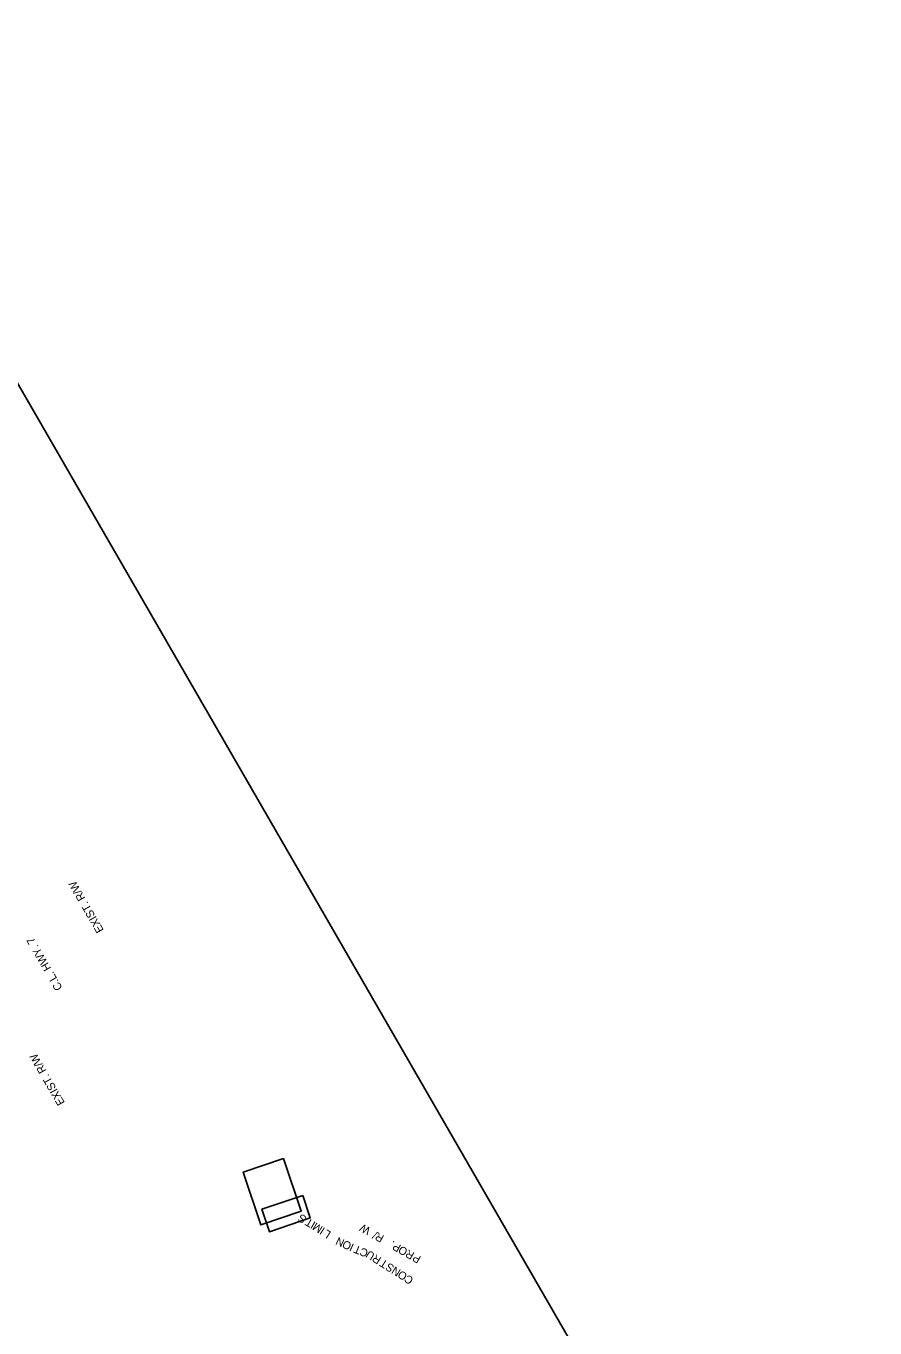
# Model space of a CAD drawing. Extents: x 956270 to 957915, y 1920230 to 1922423.
# Drawn here: x 957279 to 957915, y 1921447 to 1922423 of the extents above; entities that cross this region are included whole.
import ezdxf

# ---------------------------------------------------------------- set-up
doc = ezdxf.new("R2010")
doc.units = 0
doc.layers.add('NO PLOT', color=7, linetype='Continuous')
doc.layers.add('R_Draft', color=7, linetype='Continuous')

msp = doc.modelspace()

# ---------------------------------------------------------------- linework, layer by layer
at = {"layer": 'NO PLOT'}
for points in [[(957915.18, 1921041.6), (957117.5, 1922423.23), (956666.17, 1922162.65), (956816.66, 1921901.98), (956875.12, 1921935.73), (957087.62, 1921567.67), (957029.16, 1921533.92), (957172.25, 1921286.08), (957225.74, 1921316.96), (957397.07, 1921020.21), (957343.58, 1920989.33), (957463.85, 1920781.02)], [(957915.18, 1921041.6), (957117.5, 1922423.23), (956666.17, 1922162.65), (956816.66, 1921901.98), (956875.12, 1921935.73), (957087.62, 1921567.67), (957029.16, 1921533.92), (957172.25, 1921286.08), (957225.74, 1921316.96), (957397.07, 1921020.21), (957343.58, 1920989.33), (957463.85, 1920781.02)], [(957915.18, 1921041.6), (957117.5, 1922423.23), (956666.17, 1922162.65), (956816.66, 1921901.98), (956875.12, 1921935.73), (957087.62, 1921567.67), (957029.16, 1921533.92), (957172.25, 1921286.08), (957225.74, 1921316.96), (957397.07, 1921020.21), (957343.58, 1920989.33), (957463.85, 1920781.02)], [(957915.18, 1921041.6), (957117.5, 1922423.23), (956666.17, 1922162.65), (956816.66, 1921901.98), (956875.12, 1921935.73), (957087.62, 1921567.67), (957029.16, 1921533.92), (957172.25, 1921286.08), (957225.74, 1921316.96), (957397.07, 1921020.21), (957343.58, 1920989.33), (957463.85, 1920781.02)], [(957915.18, 1921041.6), (957117.5, 1922423.23), (956666.17, 1922162.65), (956816.66, 1921901.98), (956875.12, 1921935.73), (957087.62, 1921567.67), (957029.16, 1921533.92), (957172.25, 1921286.08), (957225.74, 1921316.96), (957397.07, 1921020.21), (957343.58, 1920989.33), (957463.85, 1920781.02)], [(957471.72, 1921573.95), (957485.01, 1921534.44), (957454.76, 1921524.27), (957441.48, 1921563.78)], [(957486.08, 1921546.25), (957491.73, 1921529.46), (957461.11, 1921519.16), (957455.46, 1921535.96)]]:
    msp.add_lwpolyline(points, close=True, dxfattribs=at)

# ---------------------------------------------------------------- texts
at = {"layer": 'R_Draft'}
for s, rotation, p in [('EXIST. R/W', 119.9486, (957337.11, 1921745.3)), ('C.L. HWY. 7', 119.98842, (957306.13, 1921702.01)), ('EXIST. R/W', 119.9486, (957307.86, 1921615.9)), ('S', 150.11499, (957489.47, 1921530.11)), ('T', 150.11499, (957494.55, 1921527.19)), ('I', 150.11499, (957496.27, 1921526.2)), ('M', 147.21381, (957501.63, 1921522.66)), ('I', 147.21381, (957503.3, 1921521.58)), ('L', 147.14191, (957507.82, 1921518.66)), ('W', 150.5183, (957537.57, 1921521.57)), ('N', 155.22135, (957517.93, 1921512.88)), ('O', 155.22135, (957523.25, 1921510.42)), ('/', 150.5183, (957542.67, 1921518.69)), ('R', 150.5183, (957547.6, 1921515.9)), ('.', 150.5183, (957555.38, 1921511.5)), ('I', 155.22135, (957525.05, 1921509.59)), ('T', 158.06906, (957530.49, 1921507.41)), ('C', 158.06906, (957535.74, 1921505.29)), ('U', 148.07095, (957540.73, 1921502.42)), ('R', 148.07095, (957545.54, 1921499.42)), ('P', 150.5183, (957560.31, 1921508.71)), ('O', 150.5183, (957565.41, 1921505.83)), ('R', 150.5183, (957570.35, 1921503.04)), ('T', 147.83322, (957550.5, 1921496.3)), ('S', 147.83322, (957555.3, 1921493.29)), ('N', 147.89904, (957560.1, 1921490.27)), ('P', 150.5183, (957575.28, 1921500.25)), ('O', 147.89904, (957565.06, 1921487.16)), ('C', 143.69438, (957569.66, 1921483.84))]:
    msp.add_text(s, height=6, rotation=rotation, dxfattribs=at).set_placement(p)

doc.saveas('drawing.dxf')
